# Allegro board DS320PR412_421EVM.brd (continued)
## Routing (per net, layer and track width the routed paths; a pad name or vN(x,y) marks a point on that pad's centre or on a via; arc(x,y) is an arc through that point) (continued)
PET3_N_A: length 150.2
  TOP w0.127: v1(106.43,30.11) 106.2,29.88 106.2,29.43 C16.2 ; v1(75.29,88.38) 75.07,88.6 75.07,89.39 75.43,89.76 J15.B28
  L4_SIG w0.102: v1(106.43,30.11) 106.2,30.33 106.2,30.86 106.43,31.09 107.72,31.09 108.04,31.42 108.04,31.6 108.22,31.78 108.48,31.78 108.65,31.6 108.65,31.42 108.98,31.09 109.44,31.09 109.77,31.42 109.77,31.6 109.95,31.78 110.2,31.78 110.38,31.6 110.38,31.42 110.71,31.09 111.17,31.09 111.5,31.42 111.5,31.6 111.68,31.78 111.93,31.78 112.11,31.6 112.11,31.42 112.44,31.09 112.9,31.09 113.23,31.42 113.23,31.6 113.4,31.78 113.66,31.78 113.84,31.6 113.84,31.42 114.16,31.09 114.63,31.09 114.95,31.42 114.95,31.6 115.13,31.78 115.38,31.78 115.56,31.6 115.56,31.42 115.89,31.09 116.35,31.09 116.68,31.42 116.68,31.6 116.86,31.78 117.11,31.78 117.29,31.6 117.29,31.42 117.62,31.09 118.08,31.09 118.41,31.42 118.41,31.6 118.59,31.78 118.84,31.78 119.02,31.6 119.02,31.42 119.34,31.09 119.81,31.09 120.13,31.42 120.13,31.6 120.31,31.78 120.57,31.78 120.74,31.6 120.74,31.42 121.07,31.09 121.53,31.09 121.86,31.42 121.86,31.6 122.04,31.78 122.29,31.78 122.47,31.6 122.47,31.42 122.8,31.09 123.26,31.09 123.59,31.42 123.59,31.6 123.77,31.78 124.02,31.78 124.2,31.6 124.2,31.42 124.53,31.09 124.99,31.09 125.32,31.42 125.32,31.6 125.49,31.78 125.75,31.78 125.93,31.6 125.93,31.42 126.25,31.09 131.19,31.09 132.29,32.19 132.29,32.65 132.02,32.92 132.02,33.17 132.2,33.35 132.45,33.35 132.72,33.08 133.19,33.08 133.52,33.41 133.52,33.87 133.24,34.14 133.24,34.4 133.42,34.58 133.68,34.58 133.95,34.3 134.41,34.3 134.74,34.63 134.74,35.1 134.47,35.37 134.47,35.62 134.65,35.8 134.9,35.8 135.17,35.53 135.63,35.53 136.55,36.44 136.55,63.23 128.91,70.87 89.08,70.87 75.06,84.89 75.06,88.15 v1(75.29,88.38)
PET3_P: length 57.4
  TOP w0.127: P5.B27 73.62,5.72 74.03,6.12 74.03,19.38 73.6,19.81 73.6,29.7 74.16,30.27 75.55,30.27 75.96,30.68 75.96,31.26 75.55,31.66 74.16,31.66 73.6,32.23 73.6,33.03 74.16,33.6 75.55,33.6 75.96,34 75.96,34.58 75.55,34.99 74.16,34.99 73.6,35.56 73.6,36.36 74.16,36.92 75.55,36.92 75.96,37.33 75.96,37.91 75.55,38.32 74.16,38.32 73.6,38.89 73.6,45.37 74.79,46.56 74.79,48.3 74.43,48.65 J16.B27
PET3_P_A: length 150.2
  TOP w0.127: v1(74.58,88.38) 74.8,88.6 74.8,89.38 74.43,89.75 J15.B27 ; v1(105.71,30.11) 105.94,29.88 105.94,29.48 C15.2
  L4_SIG w0.102: v1(105.71,30.11) 105.94,30.33 105.94,30.96 106.32,31.34 107.61,31.34 107.79,31.52 107.79,31.71 108.12,32.04 108.58,32.04 108.91,31.71 108.91,31.52 109.09,31.34 109.34,31.34 109.52,31.52 109.52,31.71 109.84,32.04 110.31,32.04 110.63,31.71 110.63,31.52 110.81,31.34 111.07,31.34 111.24,31.52 111.24,31.71 111.57,32.04 112.03,32.04 112.36,31.71 112.36,31.52 112.54,31.34 112.79,31.34 112.97,31.52 112.97,31.71 113.3,32.04 113.76,32.04 114.09,31.71 114.09,31.52 114.27,31.34 114.52,31.34 114.7,31.52 114.7,31.71 115.03,32.04 115.49,32.04 115.82,31.71 115.82,31.52 115.99,31.34 116.25,31.34 116.43,31.52 116.43,31.71 116.75,32.04 117.22,32.04 117.54,31.71 117.54,31.52 117.72,31.34 117.97,31.34 118.15,31.52 118.15,31.71 118.48,32.04 118.94,32.04 119.27,31.71 119.27,31.52 119.45,31.34 119.7,31.34 119.88,31.52 119.88,31.71 120.21,32.04 120.67,32.04 121,31.71 121,31.52 121.18,31.34 121.43,31.34 121.61,31.52 121.61,31.71 121.93,32.04 122.4,32.04 122.73,31.71 122.73,31.52 122.9,31.34 123.16,31.34 123.33,31.52 123.33,31.71 123.66,32.04 124.13,32.04 124.45,31.71 124.45,31.52 124.63,31.34 124.88,31.34 125.06,31.52 125.06,31.71 125.39,32.04 125.85,32.04 126.18,31.71 126.18,31.52 126.36,31.34 131.09,31.34 132.04,32.29 132.04,32.55 131.77,32.82 131.77,33.28 132.1,33.61 132.56,33.61 132.83,33.34 133.08,33.34 133.26,33.52 133.26,33.77 132.99,34.04 132.99,34.5 133.32,34.83 133.78,34.83 134.05,34.56 134.31,34.56 134.48,34.74 134.48,34.99 134.21,35.26 134.21,35.72 134.54,36.05 135,36.05 135.28,35.78 135.53,35.78 136.29,36.55 136.29,63.12 128.8,70.61 88.98,70.61 74.81,84.78 74.81,88.15 v1(74.58,88.38)
PET4_N: length 54
  TOP w0.127: J16.B34 81.43,48.64 81.06,48.27 81.06,42.69 80.4,42.03 80.4,41.13 81.06,40.47 81.06,38.11 89.7,29.47 89.7,15.78 80.29,6.37 80.29,6.12 80.62,5.79 P5.B34
PET4_N_A: length 160.5
  TOP w0.127: J15.B34 81.43,89.77 81.05,89.38 81.05,88.61 v1(81.29,88.38) ; v1(113.28,30.11) 113.06,29.88 113.06,29.43 C20.2
  L3_SIG w0.102: v1(113.28,30.11) 113.06,29.88 113.06,26.62 114.88,24.79 135.23,24.79 140.11,29.67 140.11,62.76 113.64,89.23 113.64,94.31 106.83,101.12 84.48,101.12 80.84,97.47 80.84,95.95 81.09,95.69 81.09,95.44 80.84,95.18 80.84,94.93 81.09,94.68 81.09,94.42 80.84,94.17 80.84,93.91 81.09,93.66 81.09,93.41 80.84,93.15 80.84,92.9 81.09,92.64 81.09,92.39 80.84,92.14 80.84,91.88 81.09,91.63 81.09,91.37 80.84,91.12 80.84,90.87 81.09,90.61 81.09,90.36 80.84,90.1 80.84,89.85 81.09,89.6 81.09,89.34 80.84,89.09 80.84,88.83 81.09,88.59 81.09,88.58 v1(81.29,88.38)
PET4_P: length 54
  TOP w0.127: J16.B33 80.43,48.64 80.8,48.27 80.8,42.8 80.14,42.14 80.14,41.02 80.8,40.36 80.8,38 89.43,29.36 89.43,15.89 80.03,6.48 80.03,6.12 79.62,5.71 P5.B33
PET4_P_A: length 160.5
  TOP w0.127: C19.2 112.8,29.48 112.8,29.88 v1(112.57,30.11) ; J15.B33 80.43,89.77 80.78,89.42 80.78,88.58 v1(80.58,88.38)
  L3_SIG w0.102: v1(80.58,88.38) 80.58,88.66 80.58,88.67 80.58,97.58 84.38,101.37 106.94,101.37 113.89,94.42 113.89,89.33 140.36,62.86 140.36,29.56 135.34,24.54 114.78,24.54 112.8,26.51 112.8,29.88 v1(112.57,30.11)
PET5_N: length 54
  TOP w0.127: J16.B38 85.43,48.65 85.08,48.3 85.08,44.09 84.51,43.52 84.14,43.52 83.73,43.11 83.73,42.53 84.14,42.12 84.51,42.12 85.08,41.56 85.08,40.76 84.51,40.19 84.14,40.19 83.73,39.78 83.73,39.21 84.14,38.8 84.51,38.8 85.08,38.23 85.08,35.62 90.64,30.05 90.64,15.1 84.29,8.75 84.29,6.12 84.62,5.79 P5.B38
PET5_N_A: length 161.2
  TOP w0.127: v1(85.29,88.38) 85.04,88.63 85.04,89.37 85.43,89.76 J15.B38 ; C25.2 117.13,29.43 117.13,29.88 v1(117.35,30.11)
  L3_SIG w0.102: v1(85.29,88.38) 85.09,88.58 85.09,88.59 84.84,88.83 84.84,89.09 85.09,89.34 85.09,89.6 84.84,89.85 84.84,90.1 85.09,90.36 85.09,90.61 84.84,90.87 84.84,91.12 85.09,91.37 85.09,91.63 84.84,91.88 84.84,92.14 85.09,92.39 85.09,92.64 84.84,92.9 84.84,93.15 85.09,93.41 85.09,93.66 84.84,93.91 84.84,94.17 85.09,94.42 85.09,94.68 84.84,94.93 84.84,95.18 85.09,95.44 85.09,95.69 84.84,95.95 84.84,97.58 87.15,99.9 103.84,99.9 109.74,93.99 109.74,89.5 138.07,61.17 138.07,47.73 138.4,47.4 139.09,47.4 139.27,47.22 139.27,46.97 139.09,46.79 138.4,46.79 138.07,46.46 138.07,46 138.4,45.67 139.09,45.67 139.27,45.49 139.27,45.24 139.09,45.06 138.4,45.06 138.07,44.73 138.07,44.27 138.4,43.94 139.09,43.94 139.27,43.77 139.27,43.51 139.09,43.33 138.4,43.33 138.07,43.01 138.07,42.54 138.4,42.22 139.09,42.22 139.27,42.04 139.27,41.79 139.09,41.61 138.4,41.61 138.07,41.28 138.07,40.82 138.4,40.49 139.09,40.49 139.27,40.31 139.27,40.06 139.09,39.88 138.4,39.88 138.07,39.55 138.07,39.09 138.4,38.76 139.09,38.76 139.27,38.58 139.27,38.33 139.09,38.15 138.4,38.15 138.07,37.83 138.07,37.36 138.4,37.04 139.09,37.04 139.27,36.86 139.27,36.6 139.09,36.43 138.4,36.43 138.07,36.1 138.07,35.64 138.4,35.31 139.09,35.31 139.27,35.13 139.27,34.88 139.09,34.7 138.4,34.7 138.07,34.37 138.07,33.91 138.4,33.58 139.09,33.58 139.27,33.4 139.27,33.15 139.09,32.97 138.4,32.97 138.07,32.64 138.07,29.92 134.14,25.98 117.83,25.98 117.12,26.7 117.12,29.88 v1(117.35,30.11)
PET5_P: length 54.1
  TOP w0.127: P5.B37 83.62,5.72 84.03,6.12 84.03,8.86 90.38,15.21 90.38,29.94 84.81,35.51 84.81,38.12 84.4,38.53 84.03,38.53 83.46,39.09 83.46,39.89 84.03,40.46 84.4,40.46 84.81,40.87 84.81,41.45 84.4,41.86 84.03,41.86 83.46,42.42 83.46,43.22 84.03,43.79 84.4,43.79 84.81,44.2 84.81,48.26 84.43,48.64 J16.B37
PET5_P_A: length 161.2
  TOP w0.127: v1(116.64,30.11) 116.86,29.88 116.86,29.48 C24.2 ; J15.B37 84.43,89.78 84.77,89.44 84.77,88.57 v1(84.58,88.38)
  L3_SIG w0.102: v1(84.58,88.38) 84.58,88.66 84.58,88.67 84.58,97.69 87.05,100.15 103.94,100.15 110,94.1 110,89.6 138.33,61.27 138.33,47.83 138.5,47.65 139.2,47.65 139.53,47.33 139.53,46.86 139.2,46.54 138.5,46.54 138.33,46.36 138.33,46.1 138.5,45.93 139.2,45.93 139.53,45.6 139.53,45.14 139.2,44.81 138.5,44.81 138.33,44.63 138.33,44.38 138.5,44.2 139.2,44.2 139.53,43.87 139.53,43.41 139.2,43.08 138.5,43.08 138.33,42.9 138.33,42.65 138.5,42.47 139.2,42.47 139.53,42.14 139.53,41.68 139.2,41.35 138.5,41.35 138.33,41.18 138.33,40.92 138.5,40.74 139.2,40.74 139.53,40.42 139.53,39.95 139.2,39.63 138.5,39.63 138.33,39.45 138.33,39.2 138.5,39.02 139.2,39.02 139.53,38.69 139.53,38.23 139.2,37.9 138.5,37.9 138.33,37.72 138.33,37.47 138.5,37.29 139.2,37.29 139.53,36.96 139.53,36.5 139.2,36.17 138.5,36.17 138.33,35.99 138.33,35.74 138.5,35.56 139.2,35.56 139.53,35.24 139.53,34.77 139.2,34.44 138.5,34.44 138.33,34.27 138.33,34.01 138.5,33.84 139.2,33.84 139.53,33.51 139.53,33.04 139.2,32.72 138.5,32.72 138.33,32.54 138.33,29.81 134.24,25.73 117.73,25.73 116.87,26.59 116.87,29.88 v1(116.64,30.11)
PET6_N: length 53.9
  TOP w0.127: P5.B42 88.62,5.79 88.29,6.12 88.29,11.1 91.49,14.3 91.49,30.84 89.07,33.26 89.07,38.15 88.5,38.71 87.52,38.71 87.11,39.12 87.11,39.7 87.52,40.11 88.5,40.11 89.07,40.67 89.07,41.47 88.5,42.04 87.52,42.04 87.11,42.45 87.11,43.03 87.52,43.44 88.5,43.44 89.07,44 89.07,45.93 89.07,45.93 89.07,48.3 89.43,48.67 J16.B42
PET6_N_A: length 161.7
  TOP w0.127: v1(121.41,30.11) 121.19,29.88 121.19,29.43 C29.2 ; J15.B42 89.43,89.76 89.04,89.37 89.04,88.65 89.1,88.59 89.1,88.57 v1(89.29,88.38)
  L3_SIG w0.102: v1(89.29,88.38) 89.09,88.58 89.09,88.59 88.84,88.83 88.84,89.09 89.09,89.34 89.09,89.6 88.84,89.85 88.84,90.1 89.09,90.36 89.09,90.61 88.84,90.87 88.84,91.12 89.09,91.37 89.09,91.63 88.84,91.88 88.84,92.14 89.09,92.39 89.09,92.64 88.84,92.9 88.84,93.15 89.09,93.41 89.09,93.66 88.84,93.91 88.84,94.17 89.09,94.42 89.09,94.68 88.84,94.93 88.84,95.18 89.09,95.44 89.09,95.69 88.84,95.95 88.84,96.76 90.76,98.68 101.67,98.68 105.82,94.53 105.82,89.29 134.67,60.45 135.1,60.45 135.98,59.57 135.98,58.53 135.8,58.35 134.9,58.35 134.58,58.02 134.58,57.56 134.9,57.23 135.8,57.23 135.98,57.05 135.98,56.8 135.8,56.62 134.9,56.62 134.58,56.3 134.58,55.83 134.9,55.51 135.8,55.51 135.98,55.33 135.98,55.07 135.8,54.9 134.9,54.9 134.58,54.57 134.58,54.11 134.9,53.78 135.8,53.78 135.98,53.6 135.98,53.35 135.8,53.17 134.9,53.17 134.58,52.84 134.58,52.38 134.9,52.05 135.8,52.05 135.98,51.87 135.98,51.62 135.8,51.44 134.9,51.44 134.58,51.11 134.58,50.65 134.9,50.32 135.8,50.32 135.98,50.14 135.98,49.89 135.8,49.71 134.9,49.71 134.58,49.39 134.58,48.92 134.9,48.6 135.8,48.6 135.98,48.42 135.98,48.17 135.8,47.99 134.9,47.99 134.58,47.66 134.58,47.2 134.9,46.87 135.8,46.87 135.98,46.69 135.98,46.44 135.8,46.26 134.9,46.26 134.58,45.93 134.58,45.47 134.9,45.14 135.8,45.14 135.98,44.96 135.98,44.71 135.8,44.53 134.9,44.53 134.58,44.21 134.58,43.74 134.9,43.41 135.8,43.41 135.98,43.24 135.98,42.98 135.8,42.81 134.9,42.81 134.58,42.48 134.58,42.01 134.9,41.69 135.8,41.69 135.98,41.51 135.98,41.26 135.8,41.08 134.9,41.08 134.58,40.75 134.58,40.29 134.9,39.96 135.8,39.96 135.98,39.78 135.98,39.53 135.8,39.35 134.9,39.35 134.58,39.02 134.58,38.56 134.9,38.23 135.8,38.23 135.98,38.05 135.98,37.8 135.8,37.62 134.9,37.62 134.58,37.3 134.58,36.83 134.9,36.51 135.8,36.51 135.98,36.33 135.98,36.07 135.8,35.9 134.9,35.9 134.58,35.57 134.58,35.11 134.9,34.78 135.8,34.78 135.98,34.6 135.98,34.35 135.8,34.17 134.9,34.17 134.58,33.84 134.58,33.38 134.9,33.05 135.8,33.05 135.98,32.87 135.98,30.34 133.05,27.41 121.74,27.41 121.18,27.97 121.18,29.88 v1(121.41,30.11)
PET6_P: length 53.9
  TOP w0.127: J16.B41 88.43,48.64 88.8,48.27 88.8,45.82 88.8,45.82 88.8,44.11 88.39,43.7 87.41,43.7 86.84,43.14 86.84,42.34 87.41,41.77 88.39,41.77 88.8,41.36 88.8,40.78 88.39,40.38 87.41,40.38 86.84,39.81 86.84,39.01 87.41,38.44 88.39,38.44 88.8,38.04 88.8,33.15 91.22,30.73 91.22,14.41 88.03,11.21 88.03,6.12 87.62,5.72 P5.B41
PET6_P_A: length 161.7
  TOP w0.127: J15.B41 88.43,89.72 88.77,89.38 88.77,88.57 v1(88.58,88.38) ; v1(120.7,30.11) 120.92,29.88 120.92,29.48 C28.2
  L3_SIG w0.102: v1(88.58,88.38) 88.58,88.66 88.58,88.67 88.58,96.86 90.66,98.94 101.78,98.94 106.08,94.63 106.08,89.4 134.77,60.71 135.2,60.71 136.23,59.68 136.23,58.42 135.91,58.1 135.01,58.1 134.83,57.92 134.83,57.66 135.01,57.49 135.91,57.49 136.23,57.16 136.23,56.7 135.91,56.37 135.01,56.37 134.83,56.19 134.83,55.94 135.01,55.76 135.91,55.76 136.23,55.43 136.23,54.97 135.91,54.64 135.01,54.64 134.83,54.46 134.83,54.21 135.01,54.03 135.91,54.03 136.23,53.7 136.23,53.24 135.91,52.91 135.01,52.91 134.83,52.74 134.83,52.48 135.01,52.3 135.91,52.3 136.23,51.98 136.23,51.51 135.91,51.19 135.01,51.19 134.83,51.01 134.83,50.76 135.01,50.58 135.91,50.58 136.23,50.25 136.23,49.79 135.91,49.46 135.01,49.46 134.83,49.28 134.83,49.03 135.01,48.85 135.91,48.85 136.23,48.52 136.23,48.06 135.91,47.73 135.01,47.73 134.83,47.55 134.83,47.3 135.01,47.12 135.91,47.12 136.23,46.8 136.23,46.33 135.91,46.01 135.01,46.01 134.83,45.83 134.83,45.57 135.01,45.4 135.91,45.4 136.23,45.07 136.23,44.61 135.91,44.28 135.01,44.28 134.83,44.1 134.83,43.85 135.01,43.67 135.91,43.67 136.23,43.34 136.23,42.88 135.91,42.55 135.01,42.55 134.83,42.37 134.83,42.12 135.01,41.94 135.91,41.94 136.23,41.61 136.23,41.15 135.91,40.82 135.01,40.82 134.83,40.65 134.83,40.39 135.01,40.21 135.91,40.21 136.23,39.89 136.23,39.42 135.91,39.1 135.01,39.1 134.83,38.92 134.83,38.67 135.01,38.49 135.91,38.49 136.23,38.16 136.23,37.7 135.91,37.37 135.01,37.37 134.83,37.19 134.83,36.94 135.01,36.76 135.91,36.76 136.23,36.43 136.23,35.97 135.91,35.64 135.01,35.64 134.83,35.46 134.83,35.21 135.01,35.03 135.91,35.03 136.23,34.71 136.23,34.24 135.91,33.92 135.01,33.92 134.83,33.74 134.83,33.48 135.01,33.31 135.91,33.31 136.23,32.98 136.23,30.23 133.15,27.15 121.64,27.15 120.93,27.86 120.93,29.88 v1(120.7,30.11)
PET7_N: length 53.9
  TOP w0.127: P5.B46 92.62,5.79 92.29,6.12 92.29,30.32 92.29,30.32 92.29,31.65 93.07,32.42 93.07,37.71 92.5,38.27 91.63,38.27 91.22,38.68 91.22,39.26 91.63,39.67 92.5,39.67 93.07,40.23 93.07,41.03 92.5,41.6 91.63,41.6 91.22,42.01 91.22,42.59 91.63,43 92.5,43 93.07,43.56 93.07,44.36 92.5,44.93 91.63,44.93 91.22,45.34 91.22,45.91 91.63,46.32 92.5,46.32 93.07,46.89 93.07,47.95 93.05,47.96 93.05,48.27 93.43,48.65 J16.B46
PET7_N_A: length 161
  TOP w0.127: v1(93.29,88.38) 93.04,88.62 93.04,89.36 93.43,89.75 J15.B46 ; C34.2 125.25,29.43 125.25,29.88 v1(125.48,30.11)
  L3_SIG w0.102: v1(93.29,88.38) 93.09,88.58 93.09,88.59 92.84,88.83 92.84,89.09 93.09,89.34 93.09,89.6 92.84,89.85 92.84,90.1 93.09,90.36 93.09,90.61 92.84,90.87 92.84,91.12 93.09,91.37 93.09,91.63 92.84,91.88 92.84,92.14 93.09,92.39 93.09,92.64 92.84,92.9 92.84,93.15 93.09,93.41 93.09,93.66 92.84,93.91 92.84,94.17 93.09,94.42 93.09,94.68 92.84,94.93 92.84,95.18 93.09,95.44 93.09,95.69 92.84,95.95 92.84,96.74 93.71,97.61 98.54,97.61 101.21,94.94 101.21,86.54 122.51,65.24 122.51,64.99 121.68,64.16 121.68,63.7 122,63.37 122.47,63.37 123.3,64.2 123.55,64.2 123.73,64.02 123.73,63.77 122.9,62.94 122.9,62.47 123.23,62.14 123.69,62.14 124.52,62.98 124.78,62.98 124.95,62.8 124.95,62.55 124.12,61.71 124.12,61.25 124.45,60.92 124.91,60.92 125.75,61.75 126,61.75 126.18,61.58 126.18,61.32 125.34,60.49 125.34,60.03 125.67,59.7 126.14,59.7 126.97,60.53 127.22,60.53 127.4,60.35 127.4,60.1 126.57,59.27 126.57,58.81 126.89,58.48 127.36,58.48 128.19,59.31 128.44,59.31 128.62,59.13 128.62,58.88 127.79,58.05 127.79,57.58 128.12,57.25 128.58,57.25 129.41,58.09 129.67,58.09 129.84,57.91 129.84,57.66 129.01,56.82 129.01,56.36 129.34,56.03 129.8,56.03 130.64,56.86 130.89,56.86 133.73,54.02 133.73,52.51 133.55,52.33 132.51,52.33 132.19,52 132.19,51.54 132.51,51.21 133.55,51.21 133.73,51.03 133.73,50.78 133.55,50.6 132.51,50.6 132.19,50.28 132.19,49.81 132.51,49.49 133.55,49.49 133.73,49.31 133.73,49.06 133.55,48.88 132.51,48.88 132.19,48.55 132.19,48.09 132.51,47.76 133.55,47.76 133.73,47.58 133.73,47.33 133.55,47.15 132.51,47.15 132.19,46.82 132.19,46.36 132.51,46.03 133.55,46.03 133.73,45.85 133.73,45.6 133.55,45.42 132.51,45.42 132.19,45.1 132.19,44.63 132.51,44.3 133.55,44.3 133.73,44.13 133.73,43.87 133.55,43.7 132.51,43.7 132.19,43.37 132.19,42.9 132.51,42.58 133.55,42.58 133.73,42.4 133.73,42.15 133.55,41.97 132.51,41.97 132.19,41.64 132.19,41.18 132.51,40.85 133.55,40.85 133.73,40.67 133.73,40.42 133.55,40.24 132.51,40.24 132.19,39.91 132.19,39.45 132.51,39.12 133.55,39.12 133.73,38.94 133.73,38.69 133.55,38.51 132.51,38.51 132.19,38.19 132.19,37.72 132.51,37.4 133.55,37.4 133.73,37.22 133.73,36.96 133.55,36.79 132.51,36.79 132.19,36.46 132.19,36 132.51,35.67 133.55,35.67 133.73,35.49 133.73,35.24 133.55,35.06 132.51,35.06 132.19,34.73 132.19,34.27 132.51,33.94 133.55,33.94 133.73,33.76 133.73,33.51 133.55,33.33 132.51,33.33 132.19,33 132.19,32.54 132.51,32.21 133.55,32.21 133.73,32.04 133.73,30.74 131.87,28.88 125.45,28.88 125.25,29.08 125.25,29.88 v1(125.48,30.11)
PET7_P: length 54
  TOP w0.127: P5.B45 91.62,5.72 92.02,6.12 92.02,30.43 92.03,30.43 92.03,31.76 92.8,32.53 92.8,37.6 92.39,38 91.52,38 90.96,38.57 90.96,39.37 91.52,39.94 92.39,39.94 92.8,40.34 92.8,40.92 92.39,41.33 91.52,41.33 90.96,41.9 90.96,42.7 91.52,43.26 92.39,43.26 92.8,43.67 92.8,44.25 92.39,44.66 91.52,44.66 90.96,45.22 90.96,46.02 91.52,46.59 92.39,46.59 92.8,47 92.8,47.84 92.79,47.85 92.79,48.28 92.43,48.64 J16.B45
PET7_P_A: length 161
  TOP w0.127: v1(92.58,88.38) 92.77,88.57 92.77,89.44 92.43,89.78 J15.B45 ; C33.2 124.99,29.48 124.99,29.88 v1(124.76,30.11)
  L3_SIG w0.102: v1(92.58,88.38) 92.58,88.66 92.58,88.67 92.58,96.85 93.6,97.87 98.64,97.87 101.46,95.04 101.46,86.65 122.76,65.35 122.76,64.89 121.93,64.05 121.93,63.8 122.11,63.62 122.36,63.62 123.19,64.45 123.66,64.45 123.99,64.13 123.99,63.66 123.15,62.83 123.15,62.58 123.33,62.4 123.58,62.4 124.42,63.23 124.88,63.23 125.21,62.9 125.21,62.44 124.38,61.61 124.38,61.36 124.56,61.18 124.81,61.18 125.64,62.01 126.1,62.01 126.43,61.68 126.43,61.22 125.6,60.39 125.6,60.13 125.78,59.95 126.03,59.95 126.86,60.79 127.33,60.79 127.65,60.46 127.65,60 126.82,59.16 126.82,58.91 127,58.73 127.25,58.73 128.08,59.56 128.55,59.56 128.88,59.24 128.88,58.77 128.04,57.94 128.04,57.69 128.22,57.51 128.47,57.51 129.31,58.34 129.77,58.34 130.1,58.01 130.1,57.55 129.27,56.72 129.27,56.47 129.45,56.29 129.7,56.29 130.53,57.12 130.99,57.12 133.99,54.13 133.99,52.4 133.66,52.08 132.62,52.08 132.44,51.9 132.44,51.65 132.62,51.47 133.66,51.47 133.99,51.14 133.99,50.68 133.66,50.35 132.62,50.35 132.44,50.17 132.44,49.92 132.62,49.74 133.66,49.74 133.99,49.41 133.99,48.95 133.66,48.62 132.62,48.62 132.44,48.44 132.44,48.19 132.62,48.01 133.66,48.01 133.99,47.69 133.99,47.22 133.66,46.9 132.62,46.9 132.44,46.72 132.44,46.46 132.62,46.29 133.66,46.29 133.99,45.96 133.99,45.5 133.66,45.17 132.62,45.17 132.44,44.99 132.44,44.74 132.62,44.56 133.66,44.56 133.99,44.23 133.99,43.77 133.66,43.44 132.62,43.44 132.44,43.26 132.44,43.01 132.62,42.83 133.66,42.83 133.99,42.5 133.99,42.04 133.66,41.71 132.62,41.71 132.44,41.54 132.44,41.28 132.62,41.1 133.66,41.1 133.99,40.78 133.99,40.31 133.66,39.99 132.62,39.99 132.44,39.81 132.44,39.56 132.62,39.38 133.66,39.38 133.99,39.05 133.99,38.59 133.66,38.26 132.62,38.26 132.44,38.08 132.44,37.83 132.62,37.65 133.66,37.65 133.99,37.32 133.99,36.86 133.66,36.53 132.62,36.53 132.44,36.35 132.44,36.1 132.62,35.92 133.66,35.92 133.99,35.6 133.99,35.13 133.66,34.81 132.62,34.81 132.44,34.63 132.44,34.37 132.62,34.2 133.66,34.2 133.99,33.87 133.99,33.41 133.66,33.08 132.62,33.08 132.44,32.9 132.44,32.65 132.62,32.47 133.66,32.47 133.99,32.14 133.99,30.63 131.98,28.63 125.35,28.63 124.99,28.98 124.99,29.88 v1(124.76,30.11)
PET8_N: length 18.9
  TOP w0.127: U1.4 98.46,19.44 98.35,19.33 98.35,17.62 97.78,17.06 97.04,17.06 96.63,16.65 96.63,16.07 97.04,15.66 97.78,15.66 98.35,15.09 98.35,8.15 97.26,7.06 97.26,6.3 97.62,5.94 P5.B51
PET8_N_B: length 21.9
  TOP w0.127: J16.B51 98.43,48.65 98.06,48.27 98.06,33.75 96.02,31.71 96.02,29.45 C6.2
PET8_P: length 18.9
  TOP w0.127: P5.B50 96.62,5.94 96.99,6.31 96.99,7.17 98.08,8.26 98.08,14.98 97.67,15.39 96.93,15.39 96.37,15.96 96.37,16.76 96.93,17.32 97.67,17.32 98.08,17.73 98.08,19.33 97.97,19.44 U1.3
PET8_P_B: length 21.9
  TOP w0.127: J16.B50 97.43,48.6 97.79,48.24 97.79,33.86 95.75,31.82 95.75,29.45 C5.2
PET9_N: length 18.8
  TOP w0.127: U1.8 100.46,19.44 100.35,19.33 100.35,14.18 101.24,13.28 101.24,10.52 100.68,9.95 99.94,9.95 99.53,9.54 99.53,8.96 99.94,8.55 100.68,8.55 101.24,7.99 101.24,6.2 101.62,5.83 P5.B55
PET9_N_B: length 22.8
  TOP w0.127: C10.2 100.08,29.45 100.08,31.68 102.07,33.67 102.07,38.93 101.5,39.5 101.44,39.5 101.03,39.91 101.03,40.49 101.44,40.9 101.5,40.9 102.07,41.46 102.07,48.27 102.43,48.64 J16.B55
PET9_P: length 18.8
  TOP w0.127: U1.7 99.97,19.44 100.08,19.33 100.08,14.07 100.98,13.17 100.98,10.63 100.57,10.22 99.83,10.22 99.26,9.65 99.26,8.85 99.83,8.29 100.57,8.29 100.98,7.88 100.98,6.21 100.62,5.85 P5.B54
PET9_P_B: length 22.8
  TOP w0.127: C9.2 99.82,29.45 99.82,31.79 101.8,33.78 101.8,38.82 101.39,39.23 101.33,39.23 100.76,39.8 100.76,40.6 101.33,41.16 101.39,41.16 101.8,41.57 101.8,48.23 101.43,48.6 J16.B54
PET10_N: length 18.8
  TOP w0.127: P5.B59 105.62,5.83 105.26,6.19 105.26,7.68 104.69,8.24 104.49,8.24 104.08,8.65 104.08,9.23 104.49,9.64 104.69,9.64 105.26,10.21 105.26,11.92 101.85,15.33 101.85,19.33 101.96,19.44 U1.11
PET10_N_B: length 22.3
  TOP w0.127: C14.2 104.15,29.45 104.15,31.63 106.03,33.52 106.03,38.66 105.47,39.22 105.47,40.2 106.06,40.79 106.06,48.22 106.43,48.6 J16.B59
PET10_P: length 18.8
  TOP w0.127: P5.B58 104.62,5.84 104.99,6.21 104.99,7.57 104.58,7.98 104.38,7.98 103.81,8.54 103.81,9.34 104.38,9.91 104.58,9.91 104.99,10.32 104.99,11.81 101.58,15.21 101.58,19.33 101.47,19.44 U1.10
PET10_P_B: length 22.3
  TOP w0.127: C13.2 103.88,29.45 103.88,31.74 105.77,33.63 105.77,38.55 105.21,39.1 105.21,40.31 105.79,40.9 105.79,48.24 105.43,48.6 J16.B58
PET11_N: length 19
  TOP w0.127: P5.B63 109.62,5.83 109.25,6.2 109.25,11.74 108.71,12.27 108.71,12.61 108.71,13.34 107.95,14.1 106.89,14.1 103.85,17.14 103.85,19.47 103.96,19.59 U1.15
PET11_N_B: length 21.8
  TOP w0.127: C18.2 108.21,29.45 108.21,31.12 110.05,32.96 110.05,48.25 110.43,48.64 J16.B63
PET11_P: length 19
  TOP w0.127: U1.14 103.47,19.55 103.58,19.43 103.58,17.03 106.78,13.83 107.84,13.83 108.44,13.23 108.44,12.61 108.44,12.16 108.98,11.63 108.98,6.18 108.62,5.83 P5.B62
PET11_P_B: length 21.8
  TOP w0.127: J16.B62 109.43,48.6 109.78,48.26 109.78,33.07 107.94,31.24 107.94,29.45 C17.2
PET12_N: length 18.5
  TOP w0.127: U2.4 117.51,19.44 117.4,19.33 117.4,12.92 116.04,11.57 114.96,11.57 114.4,11.01 114.4,9.93 113.29,8.81 113.29,6.16 113.62,5.83 P5.B67
PET12_N_B: length 22
  TOP w0.127: J16.B67 114.43,48.62 114.06,48.25 114.06,40.88 113.4,40.22 113.4,39.32 114.06,38.66 114.06,32.88 115.07,31.87 115.07,29.45 C23.2
PET12_P: length 18.5
  TOP w0.127: P5.B66 112.62,5.75 113.03,6.16 113.03,8.93 114.14,10.04 114.14,11.12 114.85,11.83 115.93,11.83 117.13,13.03 117.13,19.33 117.02,19.44 U2.3
PET12_P_B: length 22
  TOP w0.127: J16.B66 113.43,48.6 113.79,48.24 113.79,40.99 113.13,40.33 113.13,39.21 113.79,38.55 113.79,32.77 114.8,31.76 114.8,29.45 C21.2
PET13_N: length 18.3
  TOP w0.127: U2.8 119.51,19.44 119.4,19.33 119.4,13.29 117.29,11.19 117.29,9.99 116.73,9.42 116.47,9.42 116.07,9.01 116.07,8.44 116.47,8.03 116.73,8.03 117.29,7.46 117.29,6.16 117.62,5.83 P5.B71
PET13_N_B: length 22.7
  TOP w0.127: C27.2 119.13,29.45 119.13,31.92 118.05,33.01 118.05,38.31 117.48,38.87 117.26,38.87 116.85,39.28 116.85,39.86 117.26,40.27 117.48,40.27 118.05,40.83 118.05,48.25 118.43,48.63 J16.B71
PET13_P: length 18.4
  TOP w0.127: U2.7 119.02,19.44 119.13,19.33 119.13,13.4 117.03,11.3 117.03,10.1 116.62,9.69 116.36,9.69 115.8,9.12 115.8,8.32 116.36,7.76 116.62,7.76 117.03,7.35 117.03,6.16 116.62,5.75 P5.B70
PET13_P_B: length 22.7
  TOP w0.127: J16.B70 117.43,48.6 117.78,48.25 117.78,40.95 117.37,40.54 117.15,40.54 116.59,39.97 116.59,39.17 117.15,38.61 117.37,38.61 117.78,38.2 117.78,32.9 118.87,31.81 118.87,29.45 C26.2
PET14_N: length 18.4
  TOP w0.127: U2.11 121.01,19.44 120.9,19.33 120.9,13.73 121.29,13.34 121.29,11.34 120.73,10.77 120.08,10.77 119.67,10.36 119.67,9.79 120.08,9.38 120.73,9.38 121.29,8.81 121.29,6.16 121.62,5.83 P5.B75
PET14_N_B: length 22.2
  TOP w0.127: C31.2 123.2,29.45 123.2,31.72 122.03,32.88 122.03,38.52 121.17,39.38 121.17,40.07 122.03,40.93 122.03,48.25 122.43,48.65 J16.B75
PET14_P: length 18.4
  TOP w0.127: U2.10 120.52,19.44 120.63,19.33 120.63,13.62 121.03,13.23 121.03,11.45 120.62,11.04 119.97,11.04 119.41,10.47 119.41,9.68 119.97,9.11 120.62,9.11 121.03,8.7 121.03,6.16 120.62,5.75 P5.B74
PET14_P_B: length 22.2
  TOP w0.127: C30.2 122.93,29.45 122.93,31.61 121.77,32.77 121.77,38.41 120.9,39.27 120.9,40.18 121.77,41.04 121.77,48.27 121.43,48.6 J16.B74
PET15_N: length 18.5
  TOP w0.127: P5.B79 125.62,5.83 125.29,6.16 125.29,8.3 124.73,8.86 124.48,8.86 124.07,9.27 124.07,9.85 124.48,10.26 124.73,10.26 125.29,10.82 125.29,12.83 122.9,15.22 122.9,19.33 123.01,19.44 U2.15
PET15_N_B: length 21.8
  TOP w0.127: C36.2 127.26,29.45 127.26,31.87 126.07,33.06 126.07,38.51 125.72,38.86 125.72,40.22 126.07,40.57 126.07,48.25 126.43,48.61 J16.B79
PET15_P: length 18.5
  TOP w0.127: P5.B78 124.62,5.75 125.03,6.16 125.03,8.19 124.62,8.6 124.37,8.6 123.8,9.16 123.8,9.96 124.37,10.53 124.62,10.53 125.03,10.94 125.03,12.72 122.63,15.11 122.63,19.33 122.52,19.44 U2.14
PET15_P_B: length 21.8
  TOP w0.127: C35.2 126.99,29.45 126.99,31.76 125.81,32.95 125.81,38.4 125.45,38.75 125.45,40.33 125.81,40.68 125.81,48.23 125.43,48.6 J16.B78
PGOOD: length 31.2
  TOP w0.127: U7.2 v1(16.66,98.81) ; R90.2 13.76,76.02 14.18,75.59 16.52,75.59 16.99,76.06 16.99,78.95 17.16,79.12 v1(17.16,79.62) 17.16,80.12 17.28,80.25 U6.35
  L4_SIG w0.102: v1(16.66,98.81) 16.66,97.05 18.14,95.58 18.14,92.84 15.8,90.5 15.8,80.97 v1(17.16,79.62)
PRSNT1: length 102.6
  TOP w0.127: J16.A1 v1(46.43,55.42) ; J15.A1 v1(46.43,96.06)
  L3_SIG w0.102: v1(46.43,96.06) 50.01,92.48 50.01,86.71 48.13,84.83 48.13,57.11 v1(46.43,55.42) 46.43,52.57 49.47,49.53 49.47,44.88 51.5,42.86 51.5,28.67 48.26,25.43 v1(48.26,18.19)
  BOTTOM w0.127: v1(48.26,18.19) 48.26,15.5 45.9,13.14 45.9,6.15 45.62,5.87 P5.A1
PRSNT2_1: length 141
  TOP w0.127: C90.1 63.95,8.35 64.49,7.81 v1(64.49,7.31) 64.14,6.96 64.14,6.7 63.62,6.18 P5.B17 ; J18.1 J18.3 J18.5
  L4_SIG w0.102: J18.5 148.54,63.04 148.54,31.17 132.77,15.39 125.15,15.39 119.38,9.63 69.34,9.63 66.34,6.63 65.18,6.63 v1(64.49,7.31)
PRSNT2_1_A: length 100.3
  TOP w0.127: J18.2 153.97,72.75 149.43,77.29 130.1,77.29 124.76,82.63 69.27,82.63 64.43,87.46 J15.B17
PRSNT2_1_B: length 111.6
  TOP w0.229: J16.B17 v1(64.43,48.39)
  BOTTOM w0.127: J18.4 156.03,66.42 156.03,64.87 155.14,63.98 67.51,63.98 65.76,62.23 65.76,52.12 64.43,50.79 v1(64.43,48.39)
PRSNT2_2: length 133.6
  TOP w0.127: 166.22,65.86 J19.1 ; C91.1 77.47,8.58 77.85,8.2 v1(77.85,7.42) 77.85,6.92 77.62,6.69 P5.B31
  L4_SIG w0.102: 166.22,65.86 149.5,49.15 149.5,31.01 133.4,14.91 125.55,14.91 119.68,9.04 79.48,9.04 v1(77.85,7.42)
PRSNT2_2_A: length 101.1
  TOP w0.127: J19.2 168.71,70.99 168.71,74.37 166.01,77.06 155.42,77.06 154.23,78.26 131.5,78.26 125.88,83.87 83.77,83.87 78.43,89.21 J15.B31
PRSNT2_2_B: length 124.7
  TOP w0.127: J16.B31 v1(78.43,48.24)
  BOTTOM w0.127: 168.76,68.4 171.22,65.94 171.22,62.86 158.22,49.86 158.22,37.69 156.01,35.48 146.3,35.48 136.78,45.01 81.66,45.01 v1(78.43,48.24)
PRSNT2_3: length 83.4
  TOP w0.127: J20.1 J20.3 J20.5 ; P5.B48 94.62,6.18 v1(95.38,6.93) 95.38,7.92 94.74,8.56 C92.1
  L4_SIG w0.102: v1(95.38,6.93) 96.49,8.05 119.58,8.05 125.96,14.43 134.24,14.43 151.43,31.62 J20.5
PRSNT2_3_A: length 123.1
  TOP w0.127: J20.2 172.06,61.16 172.06,72.82 166.75,78.13 157.07,78.13 155.4,79.81 132.03,79.81 126.8,85.04 97.59,85.04 95.43,87.19 J15.B48
PRSNT2_3_B: length 69.2
  TOP w0.127: J16.B48 v1(95.43,48.39)
  BOTTOM w0.229: J20.4 156.13,42.7 156.13,44.09 154.53,45.69 96.67,45.69 95.43,46.93 v1(95.43,48.39)
PRSNT2_4: length 67.7
  TOP w0.127: P5.B81 127.62,5.3 127.15,5.77 127.15,6.6 v1(126.31,7.44) 126.75,7.87 C93.1 ; J21.5 J21.3 J21.1
  L4_SIG w0.102: v1(126.31,7.44) 126.31,11.53 125.88,11.96 125.88,13.41 126.26,13.79 134.75,13.79 151,30.05 158.34,30.05 J21.5
PRSNT2_4_A: length 86.5
  TOP w0.127: J15.B81 128.43,86.87 133.36,81.94 155.8,81.94 158.39,79.35 167.06,79.35 174.07,72.34 174.07,48.31 J21.2
PRSNT2_4_B: length 60.6
  TOP w0.127: J16.B81 128.43,47.31 145.03,30.71 167.39,30.71 171.04,34.37 171.04,38.48 J21.4
REFCLK_N: length 88.5
  TOP w0.127: U8.15 16.4,58.55 16.52,58.67 16.52,59.68 R119.2 16.21,60.6 16.16,60.64 v1(16.16,60.65)
  L4_SIG w0.102: v1(60.51,6.88) 60.29,7.11 60.29,7.94 58.72,9.51 49.9,9.51 49.89,9.52 44.84,14.58 39.93,14.58 25.37,29.13 25.37,34.04 20.9,38.51 20.9,52.75 19.68,53.97 19.68,57.93 18.3,59.31 18.3,61.09 17.57,61.82 16.67,61.82 16.41,61.56 16.41,60.9 v1(16.16,60.65)
  BOTTOM w0.127: v1(60.51,6.88) 60.29,6.66 60.29,6.16 60.62,5.83 P5.A14
REFCLK_P: length 88.5
  TOP w0.127: U8.14 16.9,58.56 16.79,58.67 16.79,59.67 R119.1 17.11,60.65 v1(17.12,60.65)
  L4_SIG w0.102: v1(59.8,6.88) 60.03,7.11 60.03,7.84 58.61,9.26 49.8,9.26 49.79,9.27 44.73,14.33 39.82,14.33 25.12,29.03 25.12,33.94 20.65,38.41 20.65,52.64 19.42,53.87 19.42,57.82 18.05,59.2 18.05,60.98 17.46,61.56 16.77,61.56 16.66,61.45 16.66,61.19 16.76,61.09 17.3,61.09 17.43,60.96 17.43,60.81 17.27,60.65 v1(17.12,60.65)
  BOTTOM w0.127: v1(59.8,6.88) 60.03,6.66 60.03,6.16 59.62,5.75 P5.A13
REFCLKA_N: length 80.5
  TOP w0.127: v1(26.61,55.7) R108.1 ; v1(61.29,95.58) 61.07,95.8 61.07,96.59 61.43,96.96 J15.A14
  L3_SIG w0.102: v1(26.61,55.7) 27.04,55.28 28.88,55.28 32.84,59.24 32.84,96.6 35.59,99.35 58.16,99.35 61.06,96.45 61.06,95.8 v1(61.29,95.58)
  BOTTOM w0.127: R108.1 v1(26.61,55.7)
REFCLKA_P: length 80.4
  TOP w0.127: v1(26.61,54.43) R107.1 ; v1(60.58,95.58) 60.8,95.8 60.8,96.61 60.43,96.98 J15.A13
  L3_SIG w0.102: v1(60.58,95.58) 60.81,95.8 60.81,96.34 58.05,99.1 35.7,99.1 33.1,96.49 33.1,59.13 28.99,55.02 26.8,55.02 26.61,54.84 v1(26.61,54.43)
  BOTTOM w0.127: R107.1 v1(26.61,54.43)
REFCLKB_N: length 43.2
  TOP w0.127: R110.1 v1(26.61,58.5) 26.79,58.32 26.8,58.32 26.91,58.21 28.43,58.21 34.27,64.05 57.18,64.05 61.07,60.16 61.07,58.55 61.43,58.18 J16.A14
  BOTTOM w0.127: R110.1 v1(26.61,58.5)
REFCLKB_P: length 43.3
  TOP w0.127: J16.A13 60.43,58.18 60.8,58.55 60.8,60.05 57.07,63.78 34.38,63.78 28.54,57.94 26.8,57.94 26.8,57.95 26.63,57.78 v1(26.63,57.23) R109.1
  BOTTOM w0.127: R109.1 v1(26.63,57.23)
RSV2: length 42.3
  TOP w0.127: v1(78.03,88.47) 77.43,89.06 J15.B30 ; J16.B30 v1(77.43,51.58)
  L3_SIG w0.102: v1(77.43,51.58) 78.03,52.18 78.03,54.86 78.37,55.2 78.37,55.68 78.33,55.71 78.33,56.34 76.96,57.72 76.96,66.54 78.03,67.61 v1(78.03,88.47)
RSVD: length 118.5
  TOP w0.127: P5.B82 128.62,6.46 v1(127.96,7.13) 127.91,7.18 127.91,8.54 128.02,8.65 C84.1 ; v1(129.43,48.41) J16.B82 v1(137.2,49.79) ; J15.B82 v1(129.43,89.05)
  L3_SIG w0.102: v1(129.43,48.41) 129.43,47.91 129.16,47.63 127.79,47.63 110.75,30.59 110.75,18.99 121.46,8.29 126.8,8.29 v1(127.96,7.13)
  L4_SIG w0.102: v1(137.2,49.79) 137.2,81.28 v1(129.43,89.05)
RSVD1: length 117.8
  TOP w0.127: J16.A19 66.43,58.23 v1(61.82,62.84) ; C85.1 66.49,7.95 v1(65.79,7.24) ; J15.A19 v1(66.43,96.25)
  L3_SIG w0.102: v1(60.77,12.37) 60.13,13.01 59.19,13.01 58.1,14.1 58.1,15.96 58.45,16.31 58.45,22.94 56.07,25.32 56.07,26.96 56.8,27.7 56.8,41.1 58.23,42.53 58.23,48.62 56.83,50.02 56.83,57.85 v1(61.82,62.84) 61.82,86.73 60.45,88.1 60.45,91.06 62.46,93.07 62.46,96.32 63.04,96.9 65.78,96.9 v1(66.43,96.25)
  L4_SIG w0.102: v1(65.79,7.24) 65.79,7.36 v1(60.77,12.37)
  BOTTOM w0.127: P5.A19 65.62,6.58 65.79,6.75 v1(65.79,7.24)
RSVD2: length 5.6
  TOP w0.127: C86.1 76.2,8.65 76.17,8.63 76.17,8.31 77.09,7.39 77.09,6.43 76.62,5.96 P5.B30
RSVD3: length 108.3
  TOP w0.127: v1(79.02,62.53) 79.43,62.12 J16.A32 ; v1(78.74,7.24) C87.1 ; J15.A32 v1(79.43,99.03)
  L3_SIG w0.102: v1(79.43,99.03) 78.69,98.29 78.69,88.7 79.02,88.36 v1(79.02,62.53) ; v1(78.74,7.24) 78.74,7.84 75.6,10.97 75.6,20.91 75.06,21.45 75.06,21.8 75.06,21.8 75.06,24.16 74.61,24.61 74.61,37.4 74.95,37.74 v1(74.95,43.46)
  BOTTOM w0.127: v1(74.95,43.46) 74.95,51.35 79.02,55.43 v1(79.02,62.53) ; P5.A32 78.62,6.03 79.09,6.5 79.09,6.89 v1(78.74,7.24)
RSVD4: length 111.7
  TOP w0.127: v1(79.99,62.5) 80.43,62.05 J16.A33 ; J15.A33 v1(80.43,99.03) ; v1(79.8,7.17) 80.01,7.38 C88.1
  L3_SIG w0.102: v1(75.69,43.46) 75.69,37.54 75.12,36.97 75.12,25.31 77.54,22.89 77.54,20.84 76.44,19.74 76.44,14.85 77.47,13.82 79.6,13.82 80.44,12.98 80.44,10.9 79.8,10.26 v1(79.8,7.17) ; v1(79.99,62.5) 79.99,88.11 79.15,88.95 79.15,97.31 80.43,98.59 v1(80.43,99.03)
  BOTTOM w0.127: v1(75.69,43.46) 75.69,48.79 79.99,53.09 v1(79.99,62.5) ; v1(79.8,7.17) 79.8,6.68 79.62,6.5 P5.A33
RSVD5: length 109.3
  TOP w0.127: v1(96.29,6.55) 96.52,6.77 C89.1 ; J16.A50 v1(97.43,55.61) ; J15.A50 v1(97.43,96.25)
  L3_SIG w0.102: v1(96.29,6.55) 104.11,14.36 106.55,14.36 109.09,16.91 109.09,36.39 97.43,48.05 v1(97.43,55.61) v1(97.43,96.25)
  BOTTOM w0.127: v1(96.29,6.55) 96.62,6.22 P5.A50
RX_DET_SCL_0: length 144.5
  TOP w0.127: U1.42 96.22,21.04 95.89,20.72 v1(95,20.72)
  L4_SIG w0.102: J30.1 J30.3 J30.5 J30.7 J30.9 135.64,111.07 138.31,108.4 138.31,35.95 129.98,27.62 108.51,27.62 106.15,25.26 96.05,25.26 94.18,23.38 94.18,20.96 94.42,20.72 v1(95,20.72)
RX_DET_SCL_1: length 136
  TOP w0.127: v1(111.89,21.54) 111.89,21.41 112.57,20.72 114.94,20.72 115.27,21.04 U2.42
  L4_SIG w0.102: v1(111.89,21.54) 111.89,22.22 113.8,24.14 130.44,24.14 141.3,35 141.3,96.41 156.72,111.84 J24.1 J24.3 J24.5 J24.7 J24.9
RX_DET_SCL_2: length 118
  TOP w0.127: J26.9 J26.7 J26.5 J26.3 J26.1 ; v1(56.31,21.34) 56.96,20.69 57.76,20.69 58.12,21.04 U3.42
  L4_SIG w0.102: v1(56.31,21.34) 54.89,21.34 51.85,24.38 51.85,40.94 50.46,42.33 49.62,43.16 49.62,45.33 50.35,46.06 50.35,50.6 54.58,54.84 54.58,57.53 52.12,60 52.12,87.02 51.41,87.73 51.41,90.39 54.01,92.99 54.01,103.49 62.99,112.47 J26.1
RX_DET_SCL_3: length 147.8
  TOP w0.127: v1(74.81,20.72) 76.84,20.72 77.17,21.04 U4.42 ; J28.9 J28.7 J28.5 J28.3 J28.1
  L4_SIG w0.102: v1(74.81,20.72) 73.87,20.72 70.44,24.15 55.99,24.15 54.57,25.57 54.57,39.89 58.2,43.53 58.2,51.58 59.19,52.57 59.19,54.53 57.97,55.75 57.97,88.48 64.24,94.74 69.27,94.74 82.81,108.28 87.76,108.28 94.23,114.76 J28.1
SCL: length 179.6
  TOP w0.127: J24.10 163.7,120.6 138.81,120.6 J30.10 132.46,120.6 107.57,120.6 J28.10 101.22,120.6 76.33,120.6 J26.10 ; U5.14 8.93,113.94 8.52,114.35 R79.2 v1(8.01,113.69)
  L4_SIG w0.102: J26.10 73.15,120.85 71.37,122.63 37.77,122.63 26.09,110.95 10.75,110.95 v1(8.01,113.69)
SDA: length 177.4
  TOP w0.127: J25.10 148.72,119.96 139.83,119.96 138.05,118.19 138.05,114.25 136.4,112.6 124.84,112.6 J23.10 117.86,119.58 108.2,119.58 106.93,118.31 106.93,114.38 105.16,112.6 93.57,112.6 93.34,112.83 93.34,112.85 J29.10 87,119.2 77.34,119.2 75.82,117.68 75.82,113.87 74.49,112.53 62.42,112.53 J27.10 ; U5.15 8.93,113.29 8.59,112.95 R80.2 v1(8.01,112.27)
  L4_SIG w0.102: v1(8.01,112.27) 10.7,109.58 28.09,109.58 39.24,120.73 54.23,120.73 J27.10
SEL_0: length 110.6
  TOP w0.127: U1.17 104.96,18.09 v1(105.97,17.08)
  L4_SIG w0.102: v1(161.67,80.4) 158.57,77.29 149.22,77.29 146.25,74.32 146.25,32.31 131.03,17.08 v1(105.97,17.08)
  BOTTOM w0.127: R31.2 v1(161.67,80.4)
SEL_1: length 90
  TOP w0.127: U2.17 124.01,18.52 124.36,18.18 v1(124.36,17.68)
  L4_SIG w0.102: v1(160.15,80.4) 160.15,80.21 157.99,78.05 148.59,78.05 145.69,75.16 145.69,32.64 130.73,17.68 v1(124.36,17.68)
  BOTTOM w0.127: R32.2 v1(160.15,80.4)
SEL_2: length 152.3
  TOP w0.127: v1(67.87,17.08) 66.86,18.09 U3.17
  L4_SIG w0.102: v1(164.72,80.4) 160.34,76.02 150.5,76.02 147.35,72.87 147.35,31.5 131.77,15.93 69.02,15.93 v1(67.87,17.08)
  BOTTOM w0.127: R33.2 v1(164.72,80.4)
SEL_3: length 131.4
  TOP w0.127: v1(86.92,17.08) 85.91,18.09 U4.17
  L4_SIG w0.102: v1(163.19,80.4) 159.46,76.66 149.99,76.66 146.81,73.48 146.81,31.9 131.39,16.48 87.52,16.48 v1(86.92,17.08)
  BOTTOM w0.127: R34.2 v1(163.19,80.4)
SMCLK: length 86.7
  TOP w0.127: P5.B5 49.62,9.94 48.59,10.97 48.59,16.31 v1(48.93,16.65) ; R126.1 v1(50.28,45.07) ; R122.1 v1(50.37,85.73)
  L3_SIG w0.102: v1(50.37,85.73) 48.82,84.18 48.82,53.64 50.28,52.18 v1(50.28,45.07) 51.94,43.4 51.94,28.48 48.96,25.5 48.96,16.67 v1(48.93,16.65)
SMDAT: length 87.2
  TOP w0.127: v1(51.48,85.69) 51.56,85.77 R123.1 ; v1(49.56,16.99) 49.56,16.21 49.07,15.72 49.07,11.51 50.62,9.96 P5.B6 ; R127.1 v1(51.48,45.07)
  L3_SIG w0.102: v1(49.56,16.99) 49.56,25.36 52.39,28.19 52.39,44.15 v1(51.48,45.07) 51.48,56.33 52.17,57.02 52.17,59.99 49.94,62.22 49.94,84.15 v1(51.48,85.69)
WAKE: length 85.4
  TOP w0.127: R124.1 v1(56.39,85.73) ; P5.B11 55.62,9.09 56.24,9.7 56.24,13.26 v1(55.65,13.84) ; v1(56.52,45.01) R129.1
  L3_SIG w0.102: v1(56.39,85.73) 55.13,84.47 55.13,49.23 56.52,47.85 v1(56.52,45.01) 55.09,43.58 55.09,14.4 v1(55.65,13.84)
N16637226: length 6.6
  TOP w0.127: C3.1 93.72,28.1 93.72,27.69 97.09,24.32 97.09,24.14 96.97,24.02 U1.38
N16637238: length 6.6
  TOP w0.127: C19.1 112.77,28.1 112.77,27.69 116.14,24.32 116.14,24.14 116.02,24.02 U2.38
N16637290: length 1.7
  TOP w0.127: U1.2 v1(97.46,19.25)
  BOTTOM w0.127: v1(97.46,19.25) 97.56,19.35 C1.2
N16637298: length 6.6
  TOP w0.127: C4.1 93.99,28.1 93.99,27.8 97.36,24.43 97.36,24.11 97.46,24 U1.37
N16637306: length 1.9
  TOP w0.127: U2.2 v1(116.51,19.25)
  BOTTOM w0.127: v1(116.51,19.25) 116.81,19.55 C22.2
N16637314: length 6.6
  TOP w0.127: U2.37 116.51,24 116.41,24.11 116.41,24.43 113.04,27.8 113.04,28.1 113.34,28.4 C20.1
N16637382: length 6.1
  TOP w0.127: U1.36 97.97,24.02 98.07,24.12 98.07,24.9 95.75,27.22 95.75,28.1 C5.1
N16637394: length 6.1
  TOP w0.127: U2.36 117.02,24.02 117.12,24.12 117.12,24.9 114.8,27.22 114.8,28.1 C21.1
N16637494: length 6.1
  TOP w0.127: U1.35 98.46,24 98.34,24.13 98.34,25.01 96.02,27.33 96.02,28.1 C6.1
N16637506: length 6.1
  TOP w0.127: U2.35 117.51,24 117.39,24.13 117.39,25.01 115.07,27.33 115.07,28.1 C23.1
N16637572: length 5.7
  TOP w0.127: C7.1 97.78,28.1 97.78,26.98 99.09,25.68 99.09,24.14 98.97,24.02 U1.34
N16637586: length 5.7
  TOP w0.127: U2.34 118.02,24.02 118.14,24.14 118.14,25.68 116.83,26.98 116.83,28.1 C24.1
N16637646: length 5.7
  TOP w0.127: U1.33 99.46,24 99.35,24.11 99.35,25.79 98.05,27.09 98.05,28.1 C8.1
N16637662: length 5.7
  TOP w0.127: C25.1 117.1,28.1 117.1,27.09 118.4,25.79 118.4,24.11 118.51,24 U2.33
N16637738: length 5.3
  TOP w0.127: C9.1 99.82,28.1 99.82,26.19 100.08,25.93 100.08,24.22 99.97,24.11 U1.32
N16637750: length 5.3
  TOP w0.127: U2.32 119.02,24.02 119.13,24.13 119.13,26.03 118.87,26.3 118.87,28.1 C26.1
N16637818: length 5.3
  TOP w0.127: C10.1 100.08,28.1 100.08,26.3 100.34,26.04 100.34,24.23 100.46,24.11 U1.31
N16637830: length 5.3
  TOP w0.127: C27.1 119.13,28.1 119.13,26.41 119.39,26.15 119.39,24.12 119.51,24 U2.31
N16637946: length 5.3
  TOP w0.127: C11.1 101.85,28.1 101.85,26.41 101.6,26.16 101.6,24.13 101.47,24 U1.29
N16637958: length 5.3
  TOP w0.127: C28.1 120.9,28.1 120.9,26.41 120.65,26.16 120.65,24.13 120.52,24 U2.29
N16638026: length 5.3
  TOP w0.127: C12.1 102.11,28.1 102.11,26.3 101.87,26.05 101.87,24.11 101.96,24.02 U1.28
N16638038: length 5.3
  TOP w0.127: U2.28 121.01,24.02 120.92,24.11 120.92,26.05 121.16,26.3 121.16,28.1 C29.1
N16638090: length 2
  TOP w0.127: U1.12 102.47,19.15 v1(102.41,19.1)
  BOTTOM w0.127: C2.2 102.38,19.13 v1(102.41,19.1)
N16638098: length 5.7
  TOP w0.127: U1.27 102.47,24 102.59,24.12 102.59,25.8 103.88,27.09 103.88,28.1 C13.1
N16638106: length 2.2
  TOP w0.127: v1(121.46,19.1) 121.52,19.15 U2.12
  BOTTOM w0.127: C32.2 121.25,19.31 v1(121.46,19.1)
N16638114: length 5.7
  TOP w0.127: U2.27 121.52,24 121.64,24.12 121.64,25.8 122.93,27.09 122.93,28.1 C30.1
N16638172: length 5.7
  TOP w0.127: C14.1 104.15,28.1 104.15,26.98 102.86,25.69 102.86,24.12 102.96,24.02 U1.26
N16638186: length 5.7
  TOP w0.127: C31.1 123.2,28.1 123.2,26.98 121.91,25.69 121.91,24.12 122.01,24.02 U2.26
N16638286: length 6.1
  TOP w0.127: C15.1 105.91,28.1 105.91,27.33 103.58,25 103.58,24.11 103.47,24 U1.25
N16638298: length 6.1
  TOP w0.127: U2.25 122.52,24 122.63,24.11 122.63,25 124.96,27.33 124.96,28.1 C33.1
N16638374: length 6.1
  TOP w0.127: U1.24 103.96,24.02 103.85,24.13 103.85,24.89 106.18,27.22 106.18,28.1 C16.1
N16638386: length 6.1
  TOP w0.127: C34.1 125.23,28.1 125.23,27.22 122.9,24.89 122.9,24.13 123.01,24.02 U2.24
N16638446: length 6.5
  TOP w0.127: C17.1 107.93,28.12 107.93,27.82 104.57,24.46 104.57,24.1 104.47,24 U1.23
N16638462: length 6.6
  TOP w0.127: C35.1 126.99,28.1 126.99,27.8 123.62,24.43 123.62,24.11 123.52,24 U2.23
N16638538: length 6.6
  TOP w0.127: C18.1 108.2,28.09 108.2,27.71 104.84,24.35 104.84,24.14 104.96,24.02 U1.22
N16638550: length 6.6
  TOP w0.127: C36.1 127.26,28.1 127.26,27.69 123.89,24.32 123.89,24.14 124.01,24.02 U2.22
N16641442: length 1.9
  TOP w0.127: U4.2 v1(78.41,19.25)
  BOTTOM w0.127: v1(78.41,19.25) 78.41,20.02 C53.1
N16641458: length 1.9
  TOP w0.127: U3.2 v1(59.36,19.25)
  BOTTOM w0.127: v1(59.36,19.25) 59.47,19.25 59.87,19.65 C43.1
N16641526: length 4.1
  TOP w0.127: U4.3 78.92,19.44 79.02,19.34 79.02,18.52 78.73,18.22 78.73,16.62 C54.2
N16641538: length 4.2
  TOP w0.127: C44.2 59.65,16.59 59.65,18.2 59.99,18.54 59.99,19.31 59.87,19.44 U3.3
N16641606: length 4.1
  TOP w0.127: C55.2 78.99,16.63 78.99,18.11 79.29,18.41 79.29,19.31 79.41,19.44 U4.4
N16641618: length 4.2
  TOP w0.127: C45.2 59.92,16.66 59.92,18.09 60.26,18.43 60.26,19.34 60.36,19.44 U3.4
N16641762: length 4.1
  TOP w0.127: U4.7 80.92,19.44 81.03,19.33 81.03,18.62 80.77,18.36 80.77,16.63 C56.2
N16641774: length 4.1
  TOP w0.127: C46.2 61.73,16.64 61.73,18.38 61.98,18.62 61.98,19.33 61.87,19.44 U3.7
N16641842: length 4.1
  TOP w0.127: U4.8 81.41,19.44 81.3,19.33 81.3,18.51 81.03,18.25 81.03,16.63 C57.2
N16641854: length 4.1
  TOP w0.127: U3.8 62.36,19.44 62.25,19.33 62.25,18.51 62,18.27 62,16.61 C47.2
N16641970: length 4.1
  TOP w0.127: C58.2 82.8,16.63 82.8,18.11 82.53,18.39 82.53,19.33 82.42,19.44 U4.10
N16641982: length 4.1
  TOP w0.127: U3.10 63.37,19.44 63.49,19.32 63.49,18.38 63.73,18.14 63.73,16.61 C48.2
N16642050: length 4.1
  TOP w0.127: C59.2 83.07,16.62 83.07,18.22 82.8,18.5 82.8,19.33 82.91,19.44 U4.11
N16642062: length 4.1
  TOP w0.127: C49.2 64,16.64 64,18.25 63.75,18.49 63.75,19.33 63.86,19.44 U3.11
N16642122: length 2.1
  TOP w0.127: v1(83.42,19.13) 83.42,19.2 83.42,19.21 U4.12
  BOTTOM w0.127: v1(83.42,19.13) 83.31,19.24 C60.1
N16642138: length 2
  TOP w0.127: U3.12 64.37,19.21 64.37,19.2 v1(64.37,19.13)
  BOTTOM w0.127: C50.1 64.52,19.28 v1(64.37,19.13)
N16642238: length 4.1
  TOP w0.127: U4.14 84.42,19.55 84.52,19.44 84.52,18.94 84.82,18.63 84.82,16.62 C61.2
N16642250: length 4.2
  TOP w0.127: C51.2 65.84,16.68 65.84,18.57 65.48,18.92 65.48,19.43 65.37,19.55 U3.14
N16642318: length 4.2
  TOP w0.127: C62.2 85.09,16.63 85.09,18.74 84.79,19.05 84.79,19.46 84.91,19.59 U4.15
N16642330: length 4.1
  TOP w0.127: C52.2 66.1,16.57 66.1,16.57 66.1,18.68 65.75,19.03 65.75,19.47 65.86,19.59 U3.15
N16699752: length 8.2
  BOTTOM w0.127: R34.1 R33.1 ; R34.1 JMP7.2 ; R34.1 R31.1 R32.1
N16699766: length 23.2
  TOP w0.127: J22.1 170.84,105.08 164.11,105.08 163.19,104.17 JMP8.2
  BOTTOM w0.127: R38.1 JMP8.2 ; R38.1 R35.1 R36.1 ; R38.1 R37.1
N16704207: length 11.1
  TOP w0.127: U5.12 8.71,115.24 8.31,115.65 8.31,118.57 11.3,121.56 11.3,123.72
N16704287: length 2.5
  BOTTOM w0.127: R77.1 JMP17.1
N16704327: length 22.3
  TOP w0.127: U5.13 11.72,114.59 14.25,112.06 18.21,112.06 19.15,113 19.15,118.82 21.46,121.13 P4.9
N16704339: length 15.2
  TOP w0.127: v1(11.17,115.89) U5.11 U5.10 U5.9
  BOTTOM w0.127: JMP17.2 20.24,115.57 18.44,113.77 14.1,113.77 11.97,115.89 v1(11.17,115.89)
N16704387: length 2.5
  BOTTOM w0.127: R78.1 JMP17.3
N16704399: length 16.3
  TOP w0.127: U5.5 v1(17.18,115.24)
  BOTTOM w0.127: 11.3,126.26 12.57,124.99 12.57,122.17 14.1,120.65 15.72,120.65 17.75,118.62 17.75,115.82 v1(17.18,115.24)
N16704407: length 12.3
  TOP w0.127: P4.3 13.84,122.59 13.54,122.29 13.54,114.05 14.29,113.29 U5.2
N16704427: length 14.6
  TOP w0.127: P4.6 15.16,125.04 15.16,120.07 14.12,119.02 14.12,114.3 14.48,113.94 U5.3
N16704435: length 17.2
  TOP w0.127: U5.1 17.8,112.64 18.44,113.28 18.44,119.3 20.19,121.06 20.19,124.99 P4.10
N16704743: length 5.1
  BOTTOM w0.127: J5.2 J5.4 J5.6
N16704833: length 5.1
  BOTTOM w0.127: J9.6 J9.4 J9.2
N16704863: length 5.1
  BOTTOM w0.127: J6.6 J6.4 J6.2
N16704881: length 5.1
  BOTTOM w0.127: J7.2 J7.4 J7.6
N16704899: length 5.1
  BOTTOM w0.127: J8.6 J8.4 J8.2
N16707025: length 3.6
  TOP w0.127: U6.39 19.28,79.51 18.98,79.21 R93.1 R92.2
N16707333: length 4.4
  TOP w0.127: U6.33 16.28,80.64 15.78,80.14 15.78,79.53 15.13,78.88 R88.1
  TOP w0.241: R88.1 14.61,78.38 14.54,78.45 R86.2
N16707423: length 4.2
  TOP w0.127: R82.1 23.02,81.69 23.02,81.69 R81.2 22.51,81.7 22.51,82.19 21.54,83.15 U6.4
N16707431: length 4.3
  TOP w0.127: R85.2 13.6,79.81 13.6,79.81 R84.2 14.1,80.96 14.79,81.65 U6.32
N16707493: length 1.9
  TOP w0.127: C69.1 21.94,83.66 21.93,83.65 U6.5
N16707501: length 2.6
  TOP w0.127: R91.2 17.65,78.87 17.78,79 U6.36
N16707563: length 0.6
  TOP w0.127: 22.45,85.14 C69.2
  TOP w0.229: 22.44,85.15 22.45,85.14
N16708293: length 7
  TOP w0.127: U7.4 v1(15.34,98.78) ; U7.1 v1(17.29,98.07)
  BOTTOM w0.127: v1(15.34,98.78) 15.77,98.35 R132.1 ; v1(17.29,98.07) 16.35,98.07 16.29,98.01 R132.1 ; R132.1 C105.1
N16708459: length 3
  TOP w0.127: D1.1 17.93,105.99 R83.2
N16708463: length 4.6
  TOP w0.127: D1.2 17.88,102.99 15.99,101.1 U7.3
N16708493: length 4.2
  TOP w0.127: D2.2 13.16,102.26 14.04,101.38 U7.6
N16708501: length 2.4
  TOP w0.127: U7.9 v1(14.04,95.7)
  BOTTOM w0.127: R131.2 14.05,95.08 14.04,95.08 v1(14.04,95.7)
N16708621: length 3
  TOP w0.127: R94.2 13.14,105.99 D2.1
N16712321: length 1.2
  TOP w0.127: C83.2 R95.1
N16712467: length 1.4
  TOP w0.127: C84.2 R96.1
N16712565: length 1.2
  TOP w0.127: R97.1 C85.2
N16712707: length 1.4
  TOP w0.127: C86.2 R98.1
N16712843: length 1.4
  TOP w0.127: C87.2 R99.1
N16712983: length 1.4
  TOP w0.127: C88.2 R100.1
N16713127: length 1.4
  TOP w0.127: R101.1 C89.2
N16713267: length 1.2
  TOP w0.127: R102.1 C90.2
N16713407: length 1.4
  TOP w0.127: C91.2 R103.1
N16713543: length 1.4
  TOP w0.127: R104.1 C92.2
N16713689: length 1.4
  TOP w0.127: R105.1 C93.2
N16714257: length 5.1
  BOTTOM w0.229: J17.2 J17.4 J17.6
N16716349: length 37.5
  TOP w0.127: C97.2 18.53,52.73 v1(18.49,52.77) 18.4,52.86 U8.30 ; C100.2 20.74,56.21 v1(20.73,56.21) U8.5 ; v1(21.82,54.64) C99.2 21.09,54.64 21.08,54.65 20.65,54.65 20.59,54.71 U8.2 ; U8.23 14.44,54.71 C95.2 v1(13.53,54.94) ; v1(18.91,60.06) C101.2 18.9,59.36 U8.10 ; C96.2 v1(17.32,52.76) 17.32,53.07 17.4,53.15 U8.28 ; U8.20 14.5,56.21 C94.2 v1(13.53,56.48) ; U8.32 19.4,53.42 19.75,53.08 v1(19.75,52.77) C98.2
  TOP w0.381: 20.74,56.2 v1(20.73,56.21)
  L4_SIG w0.635: 14.79,62.62 13.89,62.62 11.28,65.23 JMP19.1 1.95,67.08 1.95,74.17 JMP18.1
  vias: v1(15.6,62.99) v1(15.63,62.3) v1(16.24,62.99) v1(16.26,62.33) v1(16.88,63) v1(16.92,62.36)
N16716709: length 16.4
  TOP w0.241: U8.13 v1(17.4,59.1)
  L4_SIG w0.102: JMP19.2 8.1,58.4 16.7,58.4 v1(17.4,59.1)
N16716717: length 29.5
  TOP w0.127: v1(20.02,58.36) U8.9
  L4_SIG w0.102: JMP18.2 8.26,73.48 13.45,68.29 19.4,68.29 21.12,66.57 21.12,59.46 v1(20.02,58.36)
N16716953: length 5.4
  TOP w0.127: R107.2 24.58,54.93 23.12,54.93 22.73,55.32 20.17,55.32 U8.3
N16716991: length 5.5
  TOP w0.127: U8.4 20.16,55.6 22.83,55.6 23.23,55.19 24.59,55.19 25.08,55.68 R108.2
N16717029: length 5.7
  TOP w0.127: R109.2 24.57,57.73 23.78,57.73 22.87,56.82 22.85,56.82 22.85,56.82 20.17,56.82 U8.6
N16717077: length 5.7
  TOP w0.127: U8.7 20.19,57.07 22.74,57.07 23.68,58.01 24.61,58.01 25.08,58.48 R110.2
N16717223: length 166.2
  TOP w0.102: R118.1 v1(15.82,50.31) ; J13.1 v1(160.11,27.93)
  TOP w0.127: R118.1 15.49,51.45 15.49,52.21 15.66,52.37 16.36,52.37 16.77,52.78 16.77,53.42 U8.27
  BOTTOM w0.102: v1(15.82,50.31) 15.82,40.98 17.04,39.75 45.51,39.75 47.49,41.73 132.67,41.73 143.22,31.19 156.85,31.19 v1(160.11,27.93)
N16717247: length 158.2
  TOP w0.102: J14.1 v1(151.22,27.98) ; R118.2 v1(14.92,50.34)
  TOP w0.127: U8.26 16.5,53.45 16.5,52.88 16.26,52.63 15.55,52.63 15.24,52.32 15.24,51.45 R118.2
  BOTTOM w0.102: v1(151.22,27.98) 148.34,30.86 143.08,30.86 132.54,41.4 47.62,41.4 45.64,39.42 16.51,39.42 14.92,41.01 v1(14.92,50.34)
N16717411: length 172.2
  TOP w0.102: J12.1 v1(169,27.92) ; U8.29 v1(17.9,49.99)
  BOTTOM w0.102: v1(17.9,49.99) 17.9,40.47 18.31,40.06 45.38,40.06 47.36,42.04 132.8,42.04 143.34,31.5 165.43,31.5 v1(169,27.92)
N16717419: length 21.9
  TOP w0.127: U8.31 18.9,53.19 19.14,52.95 v1(19.14,50.05)
  L4_SIG w0.102: v1(19.14,50.05) 12.63,43.54 JMP20.2
N16717493: length 2.5
  BOTTOM w0.241: R120.2 JMP20.1
N16719912: length 3.2
  TOP w0.127: J15.B5 50.43,87.83 50.37,87.76 R122.2
N16719964: length 3.2
  TOP w0.127: J15.B6 51.43,87.89 51.56,87.76 R123.2
N16720088: length 2.5
  TOP w0.127: R121.1 J15.A11
N16720136: length 3.2
  TOP w0.127: J15.B12 59.43,87.27 R125.2
N16724044: length 3.3
  TOP w0.127: R126.2 50.28,47.1 50.43,47.25 J16.B5
N16724088: length 3.2
  TOP w0.127: R127.2 51.48,47.1 51.43,47.14 J16.B6
N16724220: length 2.5
  TOP w0.127: R128.1 J16.A11
N16724224: length 3.2
  TOP w0.127: R129.2 56.52,47.12 56.43,47.2 J16.B11
N16724268: length 3.9
  TOP w0.127: J16.B12 59.43,48.29 57.77,46.63 R130.2
N16781629: length 3.2
  TOP w0.127: J15.B11 56.43,87.31 R124.2
N16831338: length 2.9
  BOTTOM w0.127: R4.2 JMP1.8
N16831347: length 2.9
  BOTTOM w0.127: R3.1 JMP1.6
N16831350: length 2.9
  BOTTOM w0.127: R2.2 JMP1.4
N16831359: length 2.9
  BOTTOM w0.127: R1.2 JMP1.2
N16831816: length 2.9
  BOTTOM w0.127: R8.2 JMP2.8
N16831825: length 2.9
  BOTTOM w0.127: R7.1 JMP2.6
N16831828: length 2.9
  BOTTOM w0.127: R6.2 126.36,128.98
N16831837: length 2.9
  BOTTOM w0.127: R5.2 JMP2.2
